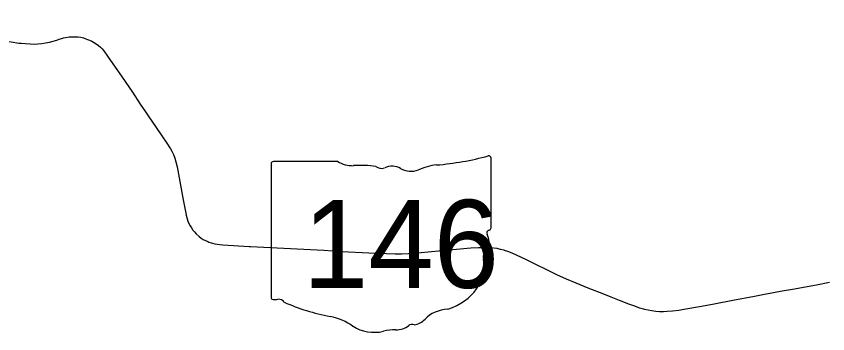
# Model space of a CAD drawing. Extents: x 2015843 to 2287843, y 623733 to 799733.
# Drawn here: x 2129505 to 2139848, y 696110 to 700155 of the extents above; entities that cross this region are included whole.
import ezdxf

# ---------------------------------------------------------------- set-up
doc = ezdxf.new("R2010")
doc.units = 0
doc.layers.add('GM_X_State_Route', color=7, linetype='Continuous')
doc.layers.add('GM_X_State_Shield', color=7, linetype='Continuous')

msp = doc.modelspace()

# ---------------------------------------------------------------- linework, layer by layer
at = {"layer": 'GM_X_State_Route'}
for points in [[(2127927, 700153), (2127937, 700153), (2127967, 700154), (2128025, 700155), (2128072, 700154), (2128117, 700153), (2128181, 700148), (2128270, 700134), (2128337, 700125), (2128401, 700112), (2128496, 700088), (2128574, 700065), (2128652, 700040), (2128807, 699989), (2128978, 699934), (2129088, 699902), (2129167, 699881), (2129263, 699859), (2129343, 699843), (2129440, 699827), (2129538, 699814), (2129568, 699811)], [(2129568, 699811), (2129619, 699806), (2129684, 699802), (2129733, 699801), (2129782, 699802), (2129831, 699807), (2129879, 699815), (2129927, 699824), (2129974, 699836), (2130005, 699846), (2130021, 699850), (2130052, 699862), (2130099, 699876), (2130107, 699878), (2130131, 699883), (2130180, 699891), (2130230, 699894), (2130263, 699894), (2130296, 699892), (2130329, 699887), (2130361, 699879), (2130393, 699869), (2130415, 699860)], [(2130415, 699860), (2130439, 699851), (2130468, 699836), (2130511, 699811), (2130552, 699783), (2130577, 699761), (2130601, 699738), (2130622, 699713), (2130670, 699646), (2130857, 699377)], [(2130857, 699377), (2130985, 699187), (2131086, 699037), (2131152, 698939), (2131195, 698874), (2131278, 698752), (2131371, 698617), (2131418, 698550), (2131471, 698466), (2131487, 698437), (2131508, 698392), (2131526, 698346), (2131540, 698299), (2131555, 698235), (2131634, 697816), (2131657, 697687), (2131661, 697666)], [(2131661, 697666), (2131670, 697623), (2131683, 697576), (2131694, 697545), (2131706, 697515), (2131721, 697486), (2131738, 697458), (2131757, 697432), (2131777, 697407), (2131799, 697383), (2131835, 697350), (2131860, 697330), (2131887, 697312), (2131916, 697297), (2131945, 697284), (2131960, 697278), (2131990, 697268), (2132006, 697264), (2132037, 697256), (2132068, 697251), (2132099, 697247), (2132137, 697241), (2132472, 697221)], [(2132472, 697221), (2132489, 697221), (2133340, 697178)], [(2133340, 697178), (2133424, 697174), (2133654, 697160), (2133997, 697141), (2134333, 697127), (2134417, 697127), (2134505, 697132), (2134624, 697140), (2134799, 697157), (2135300, 697204), (2135395, 697209), (2135468, 697211), (2135549, 697209), (2135629, 697200), (2135674, 697190), (2135718, 697179), (2135723, 697177), (2135766, 697164), (2135823, 697143), (2135996, 697061), (2136391, 696867), (2136512, 696811), (2136639, 696758), (2136792, 696697), (2136989, 696618), (2137081, 696582), (2137188, 696540), (2137310, 696492), (2137371, 696469), (2137448, 696442), (2137511, 696424), (2137559, 696413), (2137607, 696405), (2137656, 696399), (2137704, 696395), (2137753, 696394), (2137802, 696396), (2137867, 696401), (2137948, 696412), (2138013, 696422), (2138238, 696463), (2138399, 696492), (2138640, 696538), (2138913, 696589), (2139019, 696609), (2139042, 696613), (2139155, 696634), (2139268, 696655), (2139397, 696679), (2139703, 696735), (2139868, 696768)]]:
    msp.add_lwpolyline(points, dxfattribs=at)
at = {"layer": 'GM_X_State_Shield'}
for p, q in [((2132755, 698277), (2132755, 696576)), ((2133603, 698306), (2132782, 698306)), ((2135557, 697458), (2135557, 698348)), ((2135556, 697458), (2135557, 697458))]:
    msp.add_line(p, q, dxfattribs=at)
for centre, major_axis, start_param, end_param in [((2134559, 700625), (2971, 0), 4.814394, 5.042369), ((2135525, 698352), (31.2, 0), 6.141152, 7.989035), ((2132787, 698280), (32.5, 0), 1.712693, 3.28349), ((2133798, 698503), (315, 0), 4.042523, 4.731795), ((2133903, 697351), (1130, 0), 1.404758, 1.657858), ((2134293, 698093), (189, 0), 0.950623, 2.079405), ((2134937, 697786), (598, 0), 1.699011, 2.107814), ((2134159, 698289), (90.8, 0), 3.836095, 5.185415), ((2134536, 698362), (227, 0), 4.081561, 5.145723), ((2135549, 697393), (48.3, 0), 1.883978, 3.671073), ((2135523, 697455), (33.4, 0), 5.05454, 6.418171), ((2135242, 697280), (290, 0), 5.934695, 6.695948), ((2135668, 697086), (211, 0), 2.387724, 3.262537), ((2134725, 696973), (743, 0), 5.101752, 6.440018), ((2132787, 696572), (32.7, 0), 3.00124, 4.508301), ((2132792, 696746), (250, 0), 4.665946, 4.897461), ((2132843, 696477), (90.1, 0), 0.519207, 1.627899), ((2133981, 698006), (2146, 0), 4.195997, 4.488961), ((2135038, 696098), (407, 0), 1.647645, 2.488434), ((2133341, 695811), (671, 0), 0.823519, 1.323587), ((2134523, 696411), (240, 0), 4.937069, 5.64225), ((2134067, 696469), (426, 0), 4.026481, 4.996735), ((2134345, 696342), (227, 0), 4.691044, 5.507374), ((2134550, 696177), (63.9, 0), 1.147584, 2.315152), ((2134313, 695881), (350, 0), 1.495662, 1.94098)]:
    msp.add_ellipse(centre, major_axis=major_axis, ratio=0.8, start_param=start_param, end_param=end_param, dxfattribs=at)

# ---------------------------------------------------------------- texts
msp.add_text('146', height=1120.7, dxfattribs=at).set_placement((2133158, 696695))

doc.saveas('drawing.dxf')
